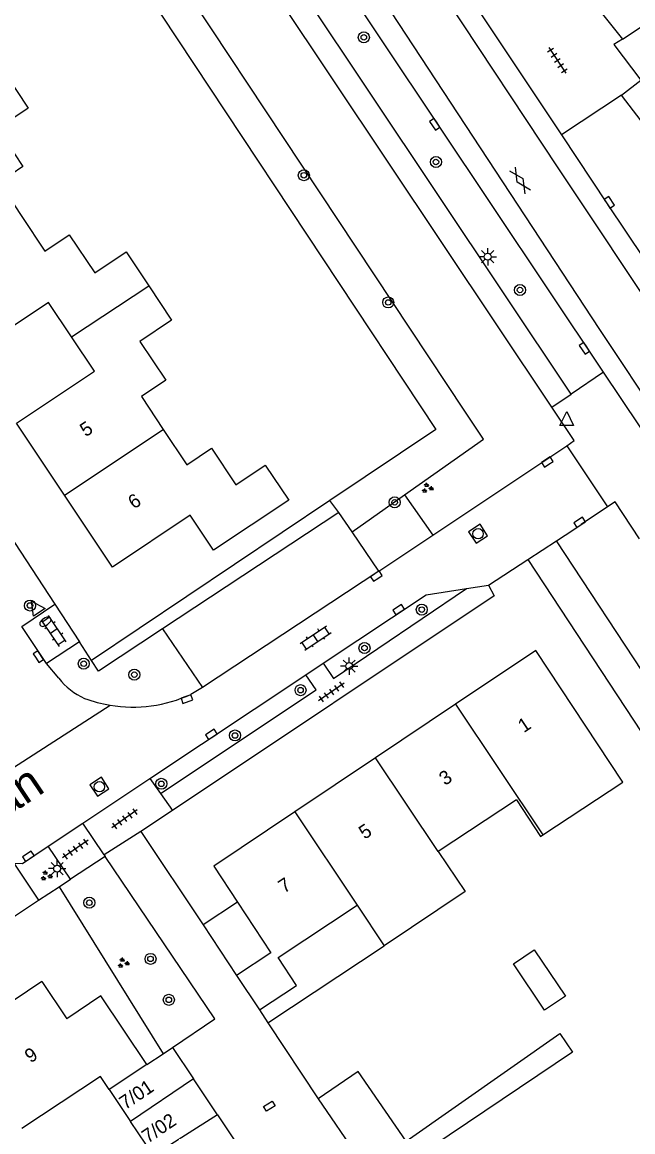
# Model space of a CAD drawing. Extents: x 137999 to 141000, y 397500 to 400501.
# Drawn here: x 138170.2 to 138214.5, y 399316.9 to 399397.3 of the extents above; entities that cross this region are included whole.
import ezdxf

# ---------------------------------------------------------------- set-up
doc = ezdxf.new("R2010")
doc.units = 0
for name, color, linetype in [('gg-afsc-erfafscheiding', 7, 'Continuous'), ('gg-anno-huisnummerreeks BGT', 7, 'Continuous'), ('gg-anno-openbare ruimte label', 7, 'Continuous'), ('gg-bbg-bijgebouw', 7, 'Continuous'), ('gg-bbg-gedigitaliseerde bebouwing', 7, 'Continuous'), ('gg-bbg-gedigitaliseerde bijgebouw', 7, 'Continuous'), ('gg-bbg-hoofdgebouw', 7, 'Continuous'), ('gg-bbg-luifel en loopbrug', 7, 'Continuous'), ('gg-bbg-tussenscheiding', 7, 'Continuous'), ('gg-knt-verharding', 7, 'Continuous'), ('gg-knt-verharding nz', 7, 'Continuous'), ('gt-grn-groengrens', 7, 'Continuous'), ('gt-grn-weggrens', 7, 'Continuous'), ('gt-symb-boom', 7, 'Continuous'), ('gt-symb-brandkraan', 7, 'Continuous'), ('gt-symb-gesloten verharding', 7, 'Continuous'), ('gt-symb-groenvak', 7, 'Continuous'), ('gt-symb-klinker verharding', 7, 'Continuous'), ('gt-symb-kolk', 7, 'Continuous'), ('gt-symb-kolk center center', 7, 'Continuous'), ('gt-symb-lichtmast', 7, 'Continuous'), ('gt-symb-rioolschacht', 7, 'Continuous'), ('gt-symb-tegel verharding', 7, 'Continuous'), ('gt-symb-waterafsluiter', 7, 'Continuous')]:
    doc.layers.add(name, color=color, linetype=linetype)

# ---------------------------------------------------------------- blocks, each defined once
blk = doc.blocks.new('gt0-BOOM')
at = {"layer": 'gt-symb-boom'}
for radius in [0.4, 0.2]:
    blk.add_circle((0, 0), radius, dxfattribs=at)
blk = doc.blocks.new('gt0-GRVAK')
at = {"layer": 'gt-symb-groenvak'}
for p, q in [((-0.11, 0.189), (-0.228, 0.24)), ((-0.182, 0.153), (0.088, 0.153)), ((-0.091, 0.211), (-0.156, 0.322)), ((-0.047, 0.214), (-0.047, 0.393)), ((-0.004, 0.211), (0.061, 0.322)), ((0.015, 0.189), (0.133, 0.24)), ((0.262, -0.052), (0.197, 0.059)), ((0.305, -0.049), (0.305, 0.13)), ((0.349, -0.052), (0.414, 0.059)), ((-0.245, -0.228), (-0.363, -0.177)), ((-0.318, -0.264), (-0.047, -0.264)), ((-0.226, -0.206), (-0.291, -0.095)), ((-0.183, -0.203), (-0.183, -0.024)), ((-0.139, -0.206), (-0.074, -0.095)), ((-0.12, -0.228), (-0.002, -0.177)), ((0.243, -0.074), (0.125, -0.023)), ((0.17, -0.11), (0.441, -0.11)), ((0.368, -0.074), (0.486, -0.023))]:
    blk.add_line(p, q, dxfattribs=at)
blk = doc.blocks.new('gt0-KOLK')
at = {"layer": 'gt-symb-kolk'}
blk.add_lwpolyline([(0, 0), (0.375, 0), (0.375, 0.4), (-0.375, 0.4), (-0.375, 0), (0, 0)], dxfattribs=at)
blk = doc.blocks.new('gt0-LMAST')
at = {"layer": 'gt-symb-lichtmast'}
for p, q in [((-0.182, 0.173), (-0.447, 0.438)), ((-0.005, 0.246), (-0.005, 0.621)), ((0.172, 0.173), (0.437, 0.438)), ((-0.255, -0.004), (-0.63, -0.004)), ((-0.182, -0.181), (-0.447, -0.446)), ((-0.005, -0.254), (-0.005, -0.629)), ((0.437, -0.446), (0.172, -0.181)), ((0.245, -0.004), (0.62, -0.004))]:
    blk.add_line(p, q, dxfattribs=at)
blk.add_circle((-0.005, -0.004), 0.25, dxfattribs=at)
blk = doc.blocks.new('gt0-GESVH1')
at = {"layer": 'gt-symb-gesloten verharding'}
for p, q in [((-0.992, -0.261), (0.008, 0.239)), ((0.008, -0.261), (-0.992, 0.239)), ((0.008, 0.239), (1.008, -0.261)), ((1.008, 0.239), (0.008, -0.261))]:
    blk.add_line(p, q, dxfattribs=at)
blk = doc.blocks.new('gt0-TEG1')
at = {"layer": 'gt-symb-tegel verharding'}
for p, q in [((-1.125, 0), (1.125, 0)), ((-0.9, -0.25), (-0.9, 0.25)), ((-0.45, -0.25), (-0.45, 0.25)), ((0, -0.25), (0, 0.25)), ((0.45, -0.25), (0.45, 0.25)), ((0.9, -0.25), (0.9, 0.25))]:
    blk.add_line(p, q, dxfattribs=at)
blk = doc.blocks.new('gt0-KL1')
at = {"layer": 'gt-symb-klinker verharding'}
for p, q in [((-1.15, 0.3), (1.15, 0.3)), ((-1, -0.3), (-1, 0.3)), ((-0.5, 0.3), (-0.5, 0.45)), ((0, -0.3), (0, 0.3)), ((0.5, 0.3), (0.5, 0.45)), ((1, -0.3), (1, 0.3)), ((-1.15, -0.3), (1.15, -0.3)), ((-0.5, -0.45), (-0.5, -0.3)), ((0.5, -0.45), (0.5, -0.3))]:
    blk.add_line(p, q, dxfattribs=at)
blk = doc.blocks.new('gt0-RS')
at = {"layer": 'gt-symb-rioolschacht'}
blk.add_lwpolyline([(-0.5, -0.5), (0.5, -0.5), (0.5, 0.5), (-0.5, 0.5)], close=True, dxfattribs=at)
blk.add_circle((0, 0), 0.375, dxfattribs=at)
blk = doc.blocks.new('gt0-WAFSL')
at = {"layer": 'gt-symb-waterafsluiter'}
for p, q in [((-0.5, -0.333), (0, 0.667)), ((0, 0.667), (0.5, -0.333)), ((0.5, -0.333), (-0.5, -0.333))]:
    blk.add_line(p, q, dxfattribs=at)
blk = doc.blocks.new('gt0-KOLKCC')
at = {"layer": 'gt-symb-kolk center center'}
blk.add_lwpolyline([(-0.375, 0.2), (0.375, 0.2), (0.375, -0.2), (-0.375, -0.2)], close=True, dxfattribs=at)
blk = doc.blocks.new('gt0-BR')
at = {"layer": 'gt-symb-brandkraan'}
for centre, radius, start, end in [((-0.244, 0), 0.206, 107.56694, 252.43307), ((0.599, -2.664), 3, 106.89205, 107.56694), ((0, -0.691), 0.938, 73.10799, 106.89205), ((-0.599, -2.664), 3, 72.43309, 73.10799), ((0.244, 0), 0.206, 287.56695, 72.43309), ((0.599, 2.664), 3, 252.43307, 253.10797), ((0, 0.691), 0.938, 253.10797, 286.89206), ((-0.599, 2.664), 3, 286.89206, 287.56695)]:
    blk.add_arc(centre, radius, start, end, dxfattribs=at)

msp = doc.modelspace()

# ---------------------------------------------------------------- linework, layer by layer
at = {"layer": 'gg-afsc-erfafscheiding'}
for p, q in [((138165.662, 399365.742), (138172.607, 399355.169)), ((138192.513, 399362.668), (138175.246, 399351.093)), ((138206.848, 399358.404), (138220.51, 399337.61)), ((138175.246, 399351.093), (138174.376, 399352.437)), ((138171.419, 399333.712), (138172.907, 399334.698)), ((138172.907, 399334.698), (138173.74, 399335.25)), ((138169.093, 399332.17), (138171.419, 399333.712))]:
    msp.add_line(p, q, dxfattribs=at)
for points in [[(138167.43, 399417.29), (138200.2, 399367.821), (138192.513, 399362.668)], [(138198.05, 399316.26), (138209.188, 399324.055), (138210.09, 399322.706), (138198.66, 399315.01)]]:
    msp.add_lwpolyline(points, dxfattribs=at)
at = {"layer": 'gg-bbg-bijgebouw'}
for p, q in [((138179.264, 399321.808), (138180.453, 399322.597)), ((138180.453, 399322.597), (138181.12, 399323.04)), ((138181.12, 399323.04), (138182.636, 399320.777)), ((138184.382, 399318.172), (138182.636, 399320.777)), ((138191.67, 399319.33), (138195.08, 399314.38)), ((138184.382, 399318.172), (138185.988, 399315.776))]:
    msp.add_line(p, q, dxfattribs=at)
msp.add_lwpolyline([(138198.05, 399316.26), (138194.56, 399321.32), (138191.67, 399319.33)], dxfattribs=at)
at = {"layer": 'gg-bbg-gedigitaliseerde bebouwing'}
for p, q in [((138207.951, 399338.449), (138213.73, 399342.26)), ((138206.029, 399340.986), (138200.373, 399337.244)), ((138194.498, 399333.361), (138196.465, 399330.418)), ((138175.898, 399320.959), (138170.22, 399317.178)), ((138176.54, 399320), (138175.898, 399320.959))]:
    msp.add_line(p, q, dxfattribs=at)
for points in [[(138168.979, 399393.654), (138170.681, 399391.105), (138168.448, 399389.614), (138170.287, 399386.86), (138168.568, 399385.712), (138170.206, 399383.259)], [(138170.206, 399383.259), (138171.882, 399380.748), (138173.651, 399381.929), (138175.49, 399379.173), (138177.759, 399380.688), (138179.411, 399378.214)], [(138179.411, 399378.214), (138181.062, 399375.74), (138178.757, 399374.202), (138180.639, 399371.383), (138178.867, 399370.199), (138180.453, 399367.824)], [(138180.453, 399367.824), (138182.16, 399365.267), (138183.949, 399366.462), (138185.715, 399363.816), (138187.84, 399365.235)], [(138206.029, 399340.986), (138207.778, 399338.335), (138207.951, 399338.449)], [(138200.373, 399337.244), (138202.317, 399334.352), (138196.465, 399330.418)], [(138187.414, 399325.768), (138190.109, 399327.55), (138188.77, 399329.574), (138194.498, 399333.361)]]:
    msp.add_lwpolyline(points, dxfattribs=at)
at = {"layer": 'gg-bbg-gedigitaliseerde bijgebouw'}
for p in [(138176.54, 399320), (138179.738, 399315.228)]:
    msp.add_line(p, (138178.093, 399317.683), dxfattribs=at)
msp.add_lwpolyline([(138205.81, 399329.11), (138207.324, 399330.128), (138209.581, 399326.771), (138208.057, 399325.747), (138205.81, 399329.11)], dxfattribs=at)
at = {"layer": 'gg-bbg-hoofdgebouw'}
for p, q in [((138201.62, 399347.916), (138195.833, 399344.037)), ((138195.833, 399344.037), (138189.983, 399340.117)), ((138189.983, 399340.117), (138184.11, 399336.18)), ((138184.11, 399336.18), (138185.824, 399333.587)), ((138185.76, 399328.271), (138187.414, 399325.768)), ((138171.65, 399327.84), (138165.737, 399323.892)), ((138171.65, 399327.84), (138173.461, 399325.129))]:
    msp.add_line(p, q, dxfattribs=at)
for points in [[(138173.81, 399374.53), (138172.15, 399377.02), (138166.5, 399373.26), (138163.025, 399378.465)], [(138173.295, 399363.055), (138169.82, 399368.27), (138175.47, 399372.04), (138173.81, 399374.53)], [(138187.84, 399365.235), (138189.54, 399362.69), (138184.09, 399359.08), (138182.41, 399361.61), (138176.77, 399357.84), (138173.295, 399363.055)], [(138213.73, 399342.26), (138207.43, 399351.81), (138201.62, 399347.916)], [(138185.824, 399333.587), (138188.25, 399329.916), (138185.76, 399328.271)], [(138179.264, 399321.808), (138175.939, 399326.785), (138173.461, 399325.129)]]:
    msp.add_lwpolyline(points, dxfattribs=at)
at = {"layer": 'gg-bbg-luifel en loopbrug'}
for p, q in [((138185.824, 399333.587), (138183.334, 399331.941)), ((138183.334, 399331.941), (138185.76, 399328.271)), ((138188.026, 399324.843), (138196.465, 399330.418)), ((138187.414, 399325.768), (138188.026, 399324.843))]:
    msp.add_line(p, q, dxfattribs=at)
at = {"layer": 'gg-bbg-tussenscheiding'}
for p, q in [((138173.81, 399374.53), (138179.411, 399378.214)), ((138173.295, 399363.055), (138180.453, 399367.824)), ((138201.62, 399347.916), (138207.951, 399338.449)), ((138200.373, 399337.244), (138195.833, 399344.037)), ((138189.983, 399340.117), (138194.498, 399333.361)), ((138179.264, 399321.808), (138176.54, 399320)), ((138182.636, 399320.777), (138178.093, 399317.683)), ((138184.382, 399318.172), (138179.738, 399315.228))]:
    msp.add_line(p, q, dxfattribs=at)
at = {"layer": 'gg-knt-verharding'}
for p, q in [((138213.725, 399396.092), (138265.247, 399430.402)), ((138208.596, 399369.433), (138173.063, 399422.675)), ((138210.591, 399400.014), (138213.725, 399396.092)), ((138203.253, 399398.223), (138209.293, 399389.157)), ((138213.634, 399392.048), (138209.293, 399389.157)), ((138212.346, 399371.97), (138210.003, 399370.372)), ((138218.705, 399362.438), (138212.346, 399371.97)), ((138208.233, 399365.67), (138209.691, 399366.627)), ((138209.691, 399366.627), (138212.623, 399362.216)), ((138199.983, 399360.165), (138208.233, 399365.67)), ((138212.623, 399362.216), (138210.728, 399360.93)), ((138193.169, 399361.815), (138180.402, 399353.375)), ((138194.136, 399360.401), (138193.169, 399361.815)), ((138196.078, 399357.56), (138194.136, 399360.401)), ((138196.078, 399357.56), (138199.983, 399360.165)), ((138206.848, 399358.404), (138208.947, 399359.762)), ((138204.01, 399356.53), (138206.848, 399358.404)), ((138202.42, 399356.29), (138204.01, 399356.53)), ((138170.208, 399353.541), (138172.607, 399355.169)), ((138172.607, 399355.169), (138174.376, 399352.437)), ((138171.992, 399350.861), (138170.208, 399353.541)), ((138180.402, 399353.375), (138183.298, 399349.141)), ((138174.376, 399352.437), (138171.992, 399350.861)), ((138172.884, 399349.794), (138171.992, 399350.861)), ((138190.784, 399350.051), (138192.035, 399350.883)), ((138179.484, 399342.533), (138190.784, 399350.051)), ((138183.298, 399349.141), (138182.452, 399348.634)), ((138174.638, 399339.309), (138179.484, 399342.533)), ((138179.484, 399342.533), (138180.254, 399341.451)), ((138180.254, 399341.451), (138181.113, 399340.221)), ((138181.113, 399340.221), (138178.83, 399338.7)), ((138172.13, 399337.64), (138174.638, 399339.309)), ((138176.167, 399337.009), (138174.638, 399339.309)), ((138178.83, 399338.7), (138176.167, 399337.009)), ((138178.83, 399338.7), (138183.334, 399331.941)), ((138173.74, 399335.25), (138172.13, 399337.64)), ((138169.624, 399336.401), (138171.419, 399333.712)), ((138176.237, 399336.896), (138173.74, 399335.25)), ((138176.167, 399337.009), (138176.237, 399336.896)), ((138188.026, 399324.843), (138191.67, 399319.33))]:
    msp.add_line(p, q, dxfattribs=at)
for points in [[(138210.003, 399370.372), (138180.921, 399413.948), (138183.27, 399415.507)], [(138212.346, 399371.97), (138188.351, 399407.926), (138185.705, 399411.869)], [(138213.725, 399396.092), (138213.091, 399395.696), (138215.043, 399393.113)], [(138243.351, 399357.011), (138234.307, 399366.323), (138228.982, 399372.311), (138225.198, 399376.935), (138213.634, 399392.048)], [(138209.293, 399389.157), (138212.601, 399384.167), (138223.458, 399367.962), (138233.715, 399352.567), (138236.65, 399348.24)], [(138209.691, 399366.627), (138210.211, 399367.013), (138208.596, 399369.433)], [(138214.943, 399359.909), (138213.174, 399362.58), (138212.623, 399362.216)], [(138208.947, 399359.762), (138210.19, 399360.565), (138210.728, 399360.93)], [(138204.01, 399356.53), (138204.43, 399355.76), (138181.113, 399340.221)], [(138192.035, 399350.883), (138192.775, 399349.793), (138202.42, 399356.29)], [(138192.035, 399350.883), (138199.5, 399355.85), (138202.42, 399356.29)], [(138180.254, 399341.451), (138191.517, 399348.957), (138190.784, 399350.051)], [(138169.624, 399336.401), (138170.25, 399336.39), (138172.13, 399337.64)], [(138181.12, 399323.04), (138184.18, 399325.12), (138176.237, 399336.896)]]:
    msp.add_lwpolyline(points, dxfattribs=at)
for centre, radius, start, end in [((138176.75, 399352.829), 4.915, 218.13211, 246.05011), ((138178.259, 399357.796), 10.087, 249.67212, 260.5729), ((138178.245, 399357.755), 10.045, 260.61475, 294.7607)]:
    msp.add_arc(centre, radius, start, end, dxfattribs=at)
at = {"layer": 'gg-knt-verharding nz'}
msp.add_line((138196.078, 399357.56), (138183.298, 399349.141), dxfattribs=at)
for points in [[(138242.734, 399338.521), (138236.79, 399345.24), (138233.078, 399351.103), (138224.612, 399363.423), (138209.061, 399386.779), (138200.973, 399399.005), (138190.338, 399414.923)], [(138187.239, 399412.88), (138212.039, 399375.052), (138220.99, 399361.633), (138227.051, 399352.921), (138233.437, 399343.349), (138234.794, 399341.072), (138237.99, 399334.883)]]:
    msp.add_lwpolyline(points, dxfattribs=at)
at = {"layer": 'gt-grn-groengrens'}
for p, q in [((138194.136, 399360.401), (138197.938, 399363.088)), ((138197.938, 399363.088), (138199.983, 399360.165)), ((138193.169, 399361.815), (138192.513, 399362.668))]:
    msp.add_line(p, q, dxfattribs=at)
for points in [[(138197.938, 399363.088), (138203.657, 399367.129), (138202.304, 399369.141), (138169.539, 399418.633)], [(138240.549, 399307.745), (138242.587, 399309.193), (138241.251, 399311.072), (138231.927, 399325.161), (138229.338, 399329.209), (138222.599, 399338.983), (138208.947, 399359.762)], [(138180.402, 399353.375), (138175.764, 399350.309), (138175.246, 399351.093)]]:
    msp.add_lwpolyline(points, dxfattribs=at)
at = {"layer": 'gt-grn-weggrens'}
for p, q in [((138213.634, 399392.048), (138215.043, 399393.113)), ((138208.596, 399369.433), (138210.003, 399370.372)), ((138167.536, 399342.004), (138176.607, 399347.845)), ((138172.907, 399334.698), (138180.453, 399322.597))]:
    msp.add_line(p, q, dxfattribs=at)

# ---------------------------------------------------------------- block references
at = {"layer": 'gt-symb-boom'}
for p in [(138194.981, 399396.226), (138200.202, 399387.198), (138190.637, 399386.237), (138206.289, 399377.922), (138196.747, 399377.023), (138197.216, 399362.541), (138170.803, 399355.067), (138199.177, 399354.771), (138195.03, 399351.988), (138174.696, 399350.851), (138178.358, 399350.057), (138190.398, 399348.937), (138185.653, 399345.654), (138180.312, 399342.153)]:
    msp.add_blockref('gt0-BOOM', p, dxfattribs=at)
for p, rotation in [((138175.101, 399333.537), -111.3543773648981), ((138179.533, 399329.47), -111.35437736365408), ((138180.858, 399326.504), -111.35437736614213)]:
    msp.add_blockref('gt0-BOOM', p, dxfattribs=dict(at, rotation=rotation))
at = {"layer": 'gt-symb-brandkraan', "rotation": 33.78542795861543}
msp.add_blockref('gt0-BR', (138171.921, 399353.901), dxfattribs=at)
at = {"layer": 'gt-symb-gesloten verharding', "rotation": -56.42118627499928}
msp.add_blockref('gt0-GESVH1', (138206.304, 399385.875), dxfattribs=at)
at = {"layer": 'gt-symb-groenvak'}
for p in [(138199.575, 399363.572), (138171.967, 399335.485), (138177.548, 399329.17)]:
    msp.add_blockref('gt0-GRVAK', p, dxfattribs=at)
at = {"layer": 'gt-symb-klinker verharding'}
for p, rotation in [((138172.533, 399353.217), 123.99203970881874), ((138191.483, 399352.715), 33.99203971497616)]:
    msp.add_blockref('gt0-KL1', p, dxfattribs=dict(at, rotation=rotation))
at = {"layer": 'gt-symb-kolk'}
for p, rotation in [((138200.286, 399390.035), 123.78542796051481), ((138212.601, 399384.167), -56.42118627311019), ((138211.129, 399373.811), 123.49940007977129), ((138208.387, 399365.297), 33.451601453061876), ((138210.728, 399360.93), 34.19864361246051), ((138195.998, 399357.029), 33.45160145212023), ((138197.623, 399354.602), 33.45160145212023), ((138171.245, 399351.255), -56.29404346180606), ((138182.095, 399348.478), -159.74525024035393), ((138184.046, 399345.565), 33.45160145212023), ((138170.788, 399336.742), 33.45160145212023)]:
    msp.add_blockref('gt0-KOLK', p, dxfattribs=dict(at, rotation=rotation))
at = {"layer": 'gt-symb-kolk center center', "rotation": 31.776143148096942}
msp.add_blockref('gt0-KOLKCC', (138188.137, 399318.807), dxfattribs=at)
at = {"layer": 'gt-symb-lichtmast'}
for p in [(138203.959, 399380.339), (138193.925, 399350.683), (138172.773, 399336.01)]:
    msp.add_blockref('gt0-LMAST', p, dxfattribs=at)
at = {"layer": 'gt-symb-rioolschacht', "rotation": 33.45160145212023}
for p in [(138203.255, 399360.268), (138175.829, 399341.942)]:
    msp.add_blockref('gt0-RS', p, dxfattribs=at)
at = {"layer": 'gt-symb-tegel verharding'}
for p, rotation in [((138208.997, 399394.562), -56.42118627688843), ((138192.629, 399348.808), -144.97512672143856), ((138177.654, 399339.616), -144.97512672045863), ((138174.083, 399337.424), -144.97512672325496)]:
    msp.add_blockref('gt0-TEG1', p, dxfattribs=dict(at, rotation=rotation))
at = {"layer": 'gt-symb-waterafsluiter'}
msp.add_blockref('gt0-WAFSL', (138209.676, 399368.451), dxfattribs=at)
at = {"layer": 'gt-symb-waterafsluiter', "rotation": 33.78542795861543}
msp.add_blockref('gt0-WAFSL', (138171.293, 399354.84), dxfattribs=at)

# ---------------------------------------------------------------- texts
at = {"layer": 'gg-anno-huisnummerreeks BGT'}
for s, rotation, p in [('5', 33.7, (138174.84, 399367.249)), ('6', 33.7, (138178.328, 399362.015)), ('1', 33.8, (138206.569, 399345.817)), ('3', 33.8, (138200.859, 399341.99)), ('5', 33.8, (138195.041, 399338.091)), ('7', 33.8, (138189.213, 399334.185)), ('9', 33.7, (138170.843, 399321.89)), ('7/01', 33.8, (138177.703, 399318.511)), ('7/02', 33.8, (138179.334, 399316.077))]:
    msp.add_text(s, height=1, rotation=rotation, dxfattribs=at).set_placement(p)
at = {"layer": 'gg-anno-openbare ruimte label'}
msp.add_text('Pieter Bruegellaan', height=2.5, rotation=33.9, dxfattribs=at).set_placement((138149.171, 399326.298))

doc.saveas('drawing.dxf')
